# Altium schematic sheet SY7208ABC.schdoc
size 127 x 101 mm
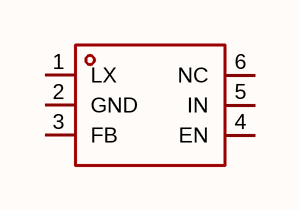
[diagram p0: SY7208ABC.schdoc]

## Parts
U?  sy7208abc  [SOT-23-6_L2.9-W1.6-P0.95-LS2.8-BR]  (value not drawn)

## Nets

Not connected (* = marked no-connect by the designer): U? 1(LX) 2(GND) 3(FB) 4(EN) 5(IN) 6(NC)

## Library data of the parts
U? = sy7208abc: 功能类型:升压型;工作电压:3V~25V;输出电压:600mV~25V;输出电流:2A;输出类型:可调;; Manufacturer: Silergy(矽力杰); AddInBom: yes; ModelId: 18da8f6c14a34920b3e136b5c401a119; ModelName: SOT-23-6_L2.9-W1.6-H1.5-LS2.8-P0.95; ModelTransform: 110.73671,114.173,0,180,0,0,0.001,-0.003,0; Function: 升压型; Voltage - Supply: 3V~25V; Output Current: 2A; Frequency - Switching: 800kHz~1.2MHz; Synchronous Rectifier: 否; Number of Outputs: 1; Topology: 升压式; Quiescent Current: 100uA; Switch tube (built-in/external): 内置; Output Type: 可调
